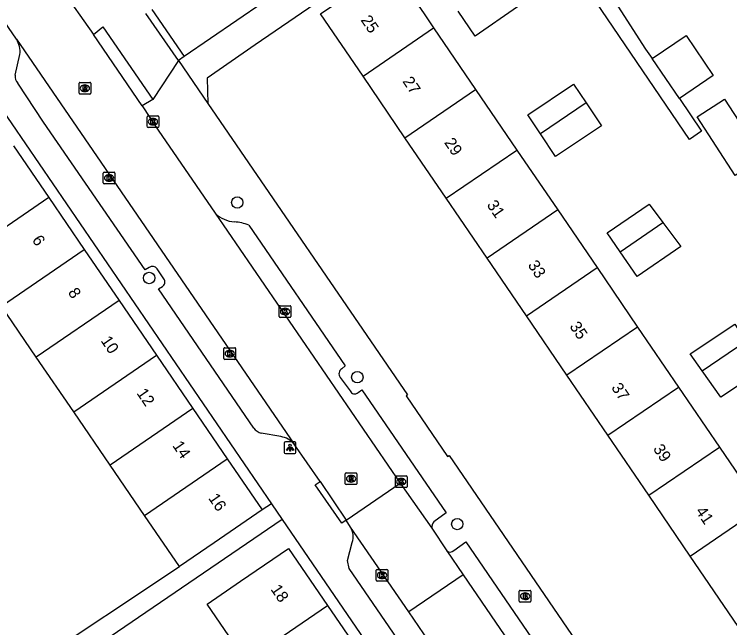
# Model space of a CAD drawing. Extents: x 157466 to 158888, y 383063 to 384677.
# Drawn here: x 158264 to 158325.5, y 383541.6 to 383594.3 of the extents above; entities that cross this region are included whole.
import ezdxf

# ---------------------------------------------------------------- set-up
doc = ezdxf.new("R2010")
doc.units = 0
for name, color, linetype in [('IMGEO_Boom', 7, 'Continuous'), ('IMGEO_Brandkraan', 7, 'Continuous'), ('IMGEO_Kolk', 7, 'Continuous'), ('IMGEO_Lichtpunt', 7, 'Continuous'), ('IMGEO_Pand', 7, 'Continuous'), ('IMGEO_Pand_nummerreeks', 7, 'Continuous'), ('IMGEO_Rijbaan_lokaal_open', 7, 'Continuous'), ('IMGEO_Rioolput', 7, 'Continuous'), ('IMGEO_Voetpad_open', 7, 'Continuous')]:
    doc.layers.add(name, color=color, linetype=linetype)

msp = doc.modelspace()

# ---------------------------------------------------------------- linework, layer by layer
at = {"layer": 'IMGEO_Boom'}
for centre in [(158283.176, 383578.158), (158275.601, 383571.669), (158293.495, 383563.147), (158302.088, 383550.528)]:
    msp.add_circle(centre, 0.489, dxfattribs=at)
at = {"layer": 'IMGEO_Brandkraan'}
for p, q in [((158307.414, 383543.907), (158307.414, 383544.759)), ((158307.489, 383544.833), (158308.341, 383544.833)), ((158307.902, 383544.613), (158307.927, 383544.613)), ((158308.415, 383544.759), (158308.415, 383543.907)), ((158308.341, 383543.833), (158307.489, 383543.833)), ((158307.925, 383544.053), (158307.9, 383544.053))]:
    msp.add_line(p, q, dxfattribs=at)
for points in [[(158307.414, 383543.907), (158307.414, 383544.759)], [(158307.489, 383544.833), (158308.341, 383544.833)], [(158307.762, 383544.533), (158307.762, 383544.133), (158307.975, 383544.133)], [(158307.993, 383544.533), (158307.762, 383544.533)], [(158307.941, 383544.452), (158307.887, 383544.452), (158307.887, 383544.376)], [(158307.887, 383544.376), (158307.94, 383544.376)], [(158307.949, 383544.3), (158307.887, 383544.3), (158307.887, 383544.219)], [(158308.415, 383544.759), (158308.415, 383543.907)], [(158308.341, 383543.833), (158307.489, 383543.833)], [(158307.887, 383544.219), (158307.949, 383544.219)]]:
    msp.add_lwpolyline(points, dxfattribs=at)
for centre, radius, start, end in [((158307.491, 383544.757), 0.0765, 91.55205, 178.44795), ((158307.491, 383544.757), 0.0765, 91.55205, 178.44795), ((158307.942, 383544.414), 0.0379, 267.82845, 90.93552), ((158307.95, 383544.259), 0.0404, 269.87594, 90.50774), ((158307.997, 383544.388), 0.145, 59.4692, 91.53667), ((158308.022, 383544.435), 0.0922, 285.51372, 58.15012), ((158308.027, 383544.243), 0.105, 301.31148, 78.98903), ((158308.339, 383544.757), 0.0765, 1.55205, 88.44795), ((158308.339, 383544.757), 0.0765, 1.55205, 88.44795), ((158307.491, 383543.909), 0.0765, 181.55205, 268.44795), ((158307.491, 383543.909), 0.0765, 181.55205, 268.44795), ((158307.981, 383544.384), 0.251, 268.66757, 293.53466), ((158308.339, 383543.909), 0.0765, 271.55205, 358.44795), ((158308.339, 383543.909), 0.0765, 271.55205, 358.44795)]:
    msp.add_arc(centre, radius, start, end, dxfattribs=at)
for centre, major_axis, ratio, start_param, end_param in [((158307.901, 383544.333), (-0.387, 0.002), 0.722429, 4.712389, 7.853982), ((158307.926, 383544.333), (-0.39, 0.002), 0.717154, 1.570796, 4.712389)]:
    msp.add_ellipse(centre, major_axis=major_axis, ratio=ratio, start_param=start_param, end_param=end_param, dxfattribs=at)
at = {"layer": 'IMGEO_Kolk'}
for p, q in [((158275.427, 383584.67), (158275.427, 383585.522)), ((158275.502, 383585.596), (158276.354, 383585.596)), ((158276.428, 383585.522), (158276.428, 383584.67)), ((158275.915, 383585.376), (158275.94, 383585.376)), ((158276.354, 383584.596), (158275.502, 383584.596)), ((158275.938, 383584.816), (158275.913, 383584.816)), ((158271.659, 383579.833), (158271.659, 383580.685)), ((158271.734, 383580.759), (158272.586, 383580.759)), ((158272.66, 383580.685), (158272.66, 383579.833)), ((158272.17, 383579.979), (158272.145, 383579.979)), ((158272.147, 383580.539), (158272.172, 383580.539)), ((158272.586, 383579.759), (158271.734, 383579.759)), ((158286.781, 383568.363), (158286.781, 383569.215)), ((158286.856, 383569.289), (158287.708, 383569.289)), ((158287.269, 383569.069), (158287.294, 383569.069)), ((158287.782, 383569.215), (158287.782, 383568.363)), ((158287.708, 383568.289), (158286.856, 383568.289)), ((158287.292, 383568.509), (158287.267, 383568.509)), ((158282.03, 383564.751), (158282.03, 383565.603)), ((158282.105, 383565.677), (158282.957, 383565.677)), ((158282.518, 383565.457), (158282.543, 383565.457)), ((158283.031, 383565.603), (158283.031, 383564.751)), ((158282.957, 383564.677), (158282.105, 383564.677)), ((158282.541, 383564.897), (158282.516, 383564.897)), ((158296.77, 383553.739), (158296.77, 383554.591)), ((158296.845, 383554.665), (158297.697, 383554.665)), ((158297.258, 383554.445), (158297.283, 383554.445)), ((158297.771, 383554.591), (158297.771, 383553.739)), ((158297.697, 383553.665), (158296.845, 383553.665)), ((158297.281, 383553.885), (158297.256, 383553.885)), ((158295.117, 383545.704), (158295.117, 383546.556)), ((158295.192, 383546.63), (158296.044, 383546.63)), ((158295.605, 383546.41), (158295.63, 383546.41)), ((158296.118, 383546.556), (158296.118, 383545.704)), ((158296.044, 383545.63), (158295.192, 383545.63)), ((158295.628, 383545.85), (158295.603, 383545.85))]:
    msp.add_line(p, q, dxfattribs=at)
for points in [[(158275.427, 383584.67), (158275.427, 383585.522)], [(158275.502, 383585.596), (158276.354, 383585.596)], [(158276.428, 383585.522), (158276.428, 383584.67)], [(158275.748, 383585.296), (158275.871, 383585.296), (158275.871, 383585.145), (158276.001, 383585.296), (158276.165, 383585.296), (158276.019, 383585.145), (158276.172, 383584.896), (158276.02, 383584.896), (158275.935, 383585.06), (158275.871, 383584.993), (158275.871, 383584.896), (158275.748, 383584.896), (158275.748, 383585.296)], [(158276.354, 383584.596), (158275.502, 383584.596)], [(158271.659, 383579.833), (158271.659, 383580.685)], [(158271.734, 383580.759), (158272.586, 383580.759)], [(158272.66, 383580.685), (158272.66, 383579.833)], [(158271.98, 383580.459), (158272.103, 383580.459), (158272.103, 383580.308), (158272.233, 383580.459), (158272.397, 383580.459), (158272.251, 383580.308), (158272.404, 383580.059), (158272.252, 383580.059), (158272.167, 383580.223), (158272.103, 383580.156), (158272.103, 383580.059), (158271.98, 383580.059), (158271.98, 383580.459)], [(158272.586, 383579.759), (158271.734, 383579.759)], [(158286.781, 383568.363), (158286.781, 383569.215)], [(158286.856, 383569.289), (158287.708, 383569.289)], [(158287.102, 383568.989), (158287.225, 383568.989), (158287.225, 383568.838), (158287.355, 383568.989), (158287.519, 383568.989), (158287.373, 383568.838), (158287.526, 383568.589), (158287.374, 383568.589), (158287.289, 383568.753), (158287.225, 383568.686), (158287.225, 383568.589), (158287.102, 383568.589), (158287.102, 383568.989)], [(158287.782, 383569.215), (158287.782, 383568.363)], [(158287.708, 383568.289), (158286.856, 383568.289)], [(158282.03, 383564.751), (158282.03, 383565.603)], [(158282.105, 383565.677), (158282.957, 383565.677)], [(158282.351, 383565.377), (158282.474, 383565.377), (158282.474, 383565.226), (158282.604, 383565.377), (158282.768, 383565.377), (158282.622, 383565.226), (158282.775, 383564.977), (158282.623, 383564.977), (158282.538, 383565.141), (158282.474, 383565.074), (158282.474, 383564.977), (158282.351, 383564.977), (158282.351, 383565.377)], [(158283.031, 383565.603), (158283.031, 383564.751)], [(158282.957, 383564.677), (158282.105, 383564.677)], [(158296.77, 383553.739), (158296.77, 383554.591)], [(158296.845, 383554.665), (158297.697, 383554.665)], [(158297.091, 383554.365), (158297.214, 383554.365), (158297.214, 383554.214), (158297.344, 383554.365), (158297.508, 383554.365), (158297.362, 383554.214), (158297.515, 383553.965), (158297.363, 383553.965), (158297.278, 383554.129), (158297.214, 383554.062), (158297.214, 383553.965), (158297.091, 383553.965), (158297.091, 383554.365)], [(158297.771, 383554.591), (158297.771, 383553.739)], [(158297.697, 383553.665), (158296.845, 383553.665)], [(158295.117, 383545.704), (158295.117, 383546.556)], [(158295.192, 383546.63), (158296.044, 383546.63)], [(158295.438, 383546.33), (158295.561, 383546.33), (158295.561, 383546.179), (158295.691, 383546.33), (158295.855, 383546.33), (158295.709, 383546.179), (158295.862, 383545.93), (158295.71, 383545.93), (158295.625, 383546.094), (158295.561, 383546.027), (158295.561, 383545.93), (158295.438, 383545.93), (158295.438, 383546.33)], [(158296.118, 383546.556), (158296.118, 383545.704)], [(158296.044, 383545.63), (158295.192, 383545.63)]]:
    msp.add_lwpolyline(points, dxfattribs=at)
for centre, start, end in [((158275.504, 383585.52), 91.55205, 178.44795), ((158275.504, 383585.52), 91.55205, 178.44795), ((158276.352, 383585.52), 1.55205, 88.44795), ((158276.352, 383585.52), 1.55205, 88.44795), ((158275.504, 383584.672), 181.55205, 268.44795), ((158275.504, 383584.672), 181.55205, 268.44795), ((158276.352, 383584.672), 271.55205, 358.44795), ((158276.352, 383584.672), 271.55205, 358.44795), ((158271.736, 383580.683), 91.55205, 178.44795), ((158271.736, 383580.683), 91.55205, 178.44795), ((158272.584, 383580.683), 1.55205, 88.44795), ((158272.584, 383580.683), 1.55205, 88.44795), ((158271.736, 383579.835), 181.55205, 268.44795), ((158271.736, 383579.835), 181.55205, 268.44795), ((158272.584, 383579.835), 271.55205, 358.44795), ((158272.584, 383579.835), 271.55205, 358.44795), ((158286.858, 383569.213), 91.55205, 178.44795), ((158286.858, 383569.213), 91.55205, 178.44795), ((158287.706, 383569.213), 1.55205, 88.44795), ((158287.706, 383569.213), 1.55205, 88.44795), ((158286.858, 383568.365), 181.55205, 268.44795), ((158286.858, 383568.365), 181.55205, 268.44795), ((158287.706, 383568.365), 271.55205, 358.44795), ((158287.706, 383568.365), 271.55205, 358.44795), ((158282.107, 383565.601), 91.55205, 178.44795), ((158282.107, 383565.601), 91.55205, 178.44795), ((158282.955, 383565.601), 1.55205, 88.44795), ((158282.955, 383565.601), 1.55205, 88.44795), ((158282.107, 383564.753), 181.55205, 268.44795), ((158282.107, 383564.753), 181.55205, 268.44795), ((158282.955, 383564.753), 271.55205, 358.44795), ((158282.955, 383564.753), 271.55205, 358.44795), ((158296.847, 383554.589), 91.55205, 178.44795), ((158296.847, 383554.589), 91.55205, 178.44795), ((158297.695, 383554.589), 1.55205, 88.44795), ((158297.695, 383554.589), 1.55205, 88.44795), ((158296.847, 383553.741), 181.55205, 268.44795), ((158296.847, 383553.741), 181.55205, 268.44795), ((158297.695, 383553.741), 271.55205, 358.44795), ((158297.695, 383553.741), 271.55205, 358.44795), ((158295.194, 383546.554), 91.55205, 178.44795), ((158295.194, 383546.554), 91.55205, 178.44795), ((158296.042, 383546.554), 1.55205, 88.44795), ((158296.042, 383546.554), 1.55205, 88.44795), ((158295.194, 383545.706), 181.55205, 268.44795), ((158295.194, 383545.706), 181.55205, 268.44795), ((158296.042, 383545.706), 271.55205, 358.44795), ((158296.042, 383545.706), 271.55205, 358.44795)]:
    msp.add_arc(centre, 0.0765, start, end, dxfattribs=at)
for centre, major_axis, ratio, start_param, end_param in [((158275.914, 383585.096), (-0.387, 0.002), 0.722429, 4.712389, 7.853982), ((158275.939, 383585.096), (-0.39, 0.002), 0.717154, 1.570796, 4.712389), ((158272.146, 383580.259), (-0.387, 0.002), 0.722429, 4.712389, 7.853982), ((158272.171, 383580.259), (-0.39, 0.002), 0.717154, 1.570796, 4.712389), ((158287.268, 383568.789), (-0.387, 0.002), 0.722429, 4.712389, 7.853982), ((158287.293, 383568.789), (-0.39, 0.002), 0.717154, 1.570796, 4.712389), ((158282.517, 383565.177), (-0.387, 0.002), 0.722429, 4.712389, 7.853982), ((158282.542, 383565.177), (-0.39, 0.002), 0.717154, 1.570796, 4.712389), ((158297.257, 383554.165), (-0.387, 0.002), 0.722429, 4.712389, 7.853982), ((158297.282, 383554.165), (-0.39, 0.002), 0.717154, 1.570796, 4.712389), ((158295.604, 383546.13), (-0.387, 0.002), 0.722429, 4.712389, 7.853982), ((158295.629, 383546.13), (-0.39, 0.002), 0.717154, 1.570796, 4.712389)]:
    msp.add_ellipse(centre, major_axis=major_axis, ratio=ratio, start_param=start_param, end_param=end_param, dxfattribs=at)
at = {"layer": 'IMGEO_Lichtpunt'}
for p, q in [((158287.218, 383557.485), (158287.218, 383556.678)), ((158287.218, 383557.485), (158287.218, 383556.678)), ((158288.12, 383557.58), (158287.312, 383557.58)), ((158288.12, 383557.58), (158287.312, 383557.58)), ((158288.214, 383556.678), (158288.214, 383557.485)), ((158288.214, 383556.678), (158288.214, 383557.485)), ((158287.312, 383556.584), (158288.12, 383556.584)), ((158287.312, 383556.584), (158288.12, 383556.584))]:
    msp.add_line(p, q, dxfattribs=at)
for points in [[(158287.592, 383557.149), (158287.631, 383557.121), (158287.443, 383556.859), (158287.405, 383556.886), (158287.592, 383557.149)], [(158287.694, 383557.101), (158287.741, 383557.101), (158287.741, 383556.779), (158287.694, 383556.779), (158287.694, 383557.101)], [(158287.804, 383557.121), (158287.842, 383557.148), (158288.029, 383556.886), (158287.99, 383556.858), (158287.804, 383557.121)]]:
    msp.add_lwpolyline(points, dxfattribs=at)
msp.add_circle((158287.717, 383557.283), 0.0994, dxfattribs=at)
for centre, start, end in [((158287.312, 383557.485), 90, 180), ((158287.312, 383557.485), 90, 180), ((158288.12, 383557.485), 0, 90), ((158288.12, 383557.485), 0, 90), ((158287.312, 383556.678), 180, 270), ((158287.312, 383556.678), 180, 270), ((158288.12, 383556.678), 270, 0), ((158288.12, 383556.678), 270, 360)]:
    msp.add_arc(centre, 0.0946, start, end, dxfattribs=at)
at = {"layer": 'IMGEO_Pand'}
for points in [[(158293.982, 383589.013), (158290.337, 383594.357), (158296.41, 383598.499), (158299.227, 383594.369), (158300.055, 383593.156)], [(158305.807, 383597.08), (158307.269, 383594.953), (158303.615, 383592.442), (158302.17, 383594.6)], [(158293.982, 383589.013), (158300.055, 383593.156)], [(158300.055, 383593.156), (158303.664, 383587.864)], [(158318.835, 383590.526), (158321.755, 383592.509), (158324.096, 383589.061), (158321.177, 383587.078)], [(158321.177, 383587.078), (158318.835, 383590.526)], [(158297.591, 383583.722), (158293.982, 383589.013)], [(158309.238, 383584.046), (158308.143, 383585.681), (158312.082, 383588.319), (158313.154, 383586.717)], [(158297.591, 383583.722), (158303.664, 383587.864)], [(158303.664, 383587.864), (158307.212, 383582.663)], [(158322.707, 383585.502), (158325.052, 383587.032), (158328.329, 383582.009), (158325.984, 383580.479), (158324.339, 383582.986), (158322.707, 383585.502)], [(158313.154, 383586.717), (158314.475, 383584.745), (158310.536, 383582.108), (158309.238, 383584.046)], [(158313.154, 383586.717), (158309.238, 383584.046)], [(158301.139, 383578.52), (158297.591, 383583.722)], [(158263.932, 383583.024), (158266.973, 383578.575)], [(158301.139, 383578.52), (158307.212, 383582.663)], [(158307.212, 383582.663), (158310.726, 383577.511)], [(158266.973, 383578.575), (158259.856, 383573.712)], [(158266.973, 383578.575), (158270.026, 383574.107)], [(158304.653, 383573.369), (158301.139, 383578.52)], [(158310.726, 383577.511), (158304.653, 383573.369)], [(158310.726, 383577.511), (158314.099, 383572.565)], [(158316.079, 383573.916), (158314.969, 383575.538), (158318.593, 383578.011), (158319.769, 383576.433)], [(158319.769, 383576.433), (158321.313, 383574.362), (158317.537, 383571.786), (158316.079, 383573.916)], [(158316.079, 383573.916), (158319.769, 383576.433)], [(158262.909, 383569.245), (158270.026, 383574.107)], [(158270.026, 383574.107), (158273.013, 383569.736)], [(158308.027, 383568.422), (158304.653, 383573.369)], [(158308.027, 383568.422), (158314.099, 383572.565)], [(158314.099, 383572.565), (158317.588, 383567.449)], [(158273.013, 383569.736), (158265.897, 383564.872)], [(158273.013, 383569.736), (158276.233, 383565.025)], [(158265.897, 383564.872), (158262.909, 383569.245)], [(158311.516, 383563.307), (158308.027, 383568.422)], [(158323.139, 383563.688), (158322.108, 383565.153), (158325.947, 383567.696), (158326.902, 383566.255)], [(158317.588, 383567.449), (158311.516, 383563.307)], [(158317.588, 383567.449), (158321.102, 383562.298)], [(158326.902, 383566.255), (158328.465, 383563.895), (158324.733, 383561.423), (158323.139, 383563.688)], [(158323.139, 383563.688), (158326.902, 383566.255)], [(158269.115, 383560.163), (158265.897, 383564.872)], [(158269.115, 383560.163), (158276.233, 383565.025)], [(158276.233, 383565.025), (158279.354, 383560.458)], [(158315.03, 383558.156), (158311.516, 383563.307)], [(158315.03, 383558.156), (158321.102, 383562.298)], [(158321.102, 383562.298), (158324.617, 383557.144)], [(158279.354, 383560.458), (158272.237, 383555.595)], [(158279.354, 383560.458), (158282.316, 383556.124)], [(158272.237, 383555.595), (158269.115, 383560.163)], [(158318.545, 383553.002), (158315.03, 383558.156)], [(158318.545, 383553.002), (158324.617, 383557.144)], [(158324.617, 383557.144), (158328.18, 383551.921)], [(158275.199, 383551.26), (158282.316, 383556.124)], [(158282.316, 383556.124), (158285.312, 383551.74)], [(158275.199, 383551.26), (158272.237, 383555.595)], [(158322.107, 383547.78), (158318.545, 383553.002)], [(158285.312, 383551.74), (158281.184, 383548.919), (158278.195, 383546.876)], [(158328.18, 383551.921), (158332.308, 383545.869), (158330.367, 383544.545), (158326.236, 383541.727), (158322.107, 383547.78)], [(158322.107, 383547.78), (158328.18, 383551.921)], [(158278.195, 383546.876), (158275.199, 383551.26)], [(158283.933, 383538.753), (158280.582, 383543.656), (158283.45, 383545.616), (158287.578, 383548.437), (158290.929, 383543.534)], [(158283.933, 383538.753), (158290.929, 383543.534)], [(158290.929, 383543.534), (158294.049, 383538.968)]]:
    msp.add_lwpolyline(points, dxfattribs=at)
at = {"layer": 'IMGEO_Rijbaan_lokaal_open'}
for points in [[(158333.171, 383627.939), (158309.83, 383612.03), (158306.706, 383609.901), (158296.72, 383603.094), (158278.623, 383590.71)], [(158264.184, 383592.177), (158263.501, 383593.197), (158262.585, 383594.528), (158261, 383596.831), (158259.046, 383599.735), (158258.908, 383599.874)], [(158267.986, 383596.629), (158270.806, 383592.574)], [(158275.823, 383594.75), (158278.623, 383590.71)], [(158278.116, 383590.363), (158275.305, 383594.395)], [(158274.995, 383586.467), (158270.806, 383592.574)], [(158264.184, 383592.177), (158288.053, 383557.407)], [(158278.623, 383590.71), (158278.116, 383590.363)], [(158274.995, 383586.467), (158276.368, 383584.356), (158281.287, 383577.232)], [(158281.287, 383577.232), (158297.166, 383554.041)], [(158290.293, 383554.184), (158288.053, 383557.407)], [(158290.293, 383554.184), (158292.53, 383550.856)], [(158292.53, 383550.856), (158297.166, 383554.041)], [(158297.166, 383554.041), (158299.891, 383550.174)], [(158292.914, 383550.25), (158292.53, 383550.856)], [(158297.921, 383542.978), (158292.914, 383550.25)], [(158299.891, 383550.174), (158301.18, 383548.218)], [(158301.18, 383548.218), (158302.597, 383546.178)], [(158302.597, 383546.178), (158297.921, 383542.978)], [(158302.597, 383546.178), (158310.512, 383534.601)], [(158317.262, 383514.634), (158297.921, 383542.978)]]:
    msp.add_lwpolyline(points, dxfattribs=at)
at = {"layer": 'IMGEO_Rioolput'}
for p, q in [((158269.575, 383587.548), (158269.575, 383588.4)), ((158269.65, 383588.474), (158270.502, 383588.474)), ((158270.063, 383588.254), (158270.088, 383588.254)), ((158270.576, 383588.4), (158270.576, 383587.548)), ((158270.502, 383587.474), (158269.65, 383587.474)), ((158270.086, 383587.694), (158270.061, 383587.694)), ((158292.456, 383553.996), (158292.456, 383554.848)), ((158292.531, 383554.922), (158293.383, 383554.922)), ((158293.457, 383554.848), (158293.457, 383553.996)), ((158292.967, 383554.142), (158292.942, 383554.142)), ((158292.944, 383554.702), (158292.969, 383554.702)), ((158293.383, 383553.922), (158292.531, 383553.922))]:
    msp.add_line(p, q, dxfattribs=at)
for points in [[(158269.575, 383587.548), (158269.575, 383588.4)], [(158269.65, 383588.474), (158270.502, 383588.474)], [(158270.164, 383588.172), (158269.912, 383588.174), (158269.912, 383587.774)], [(158270.09, 383588.093), (158270.036, 383588.093), (158270.036, 383588.012)], [(158270.036, 383588.012), (158270.088, 383588.012)], [(158270.576, 383588.4), (158270.576, 383587.548)], [(158270.502, 383587.474), (158269.65, 383587.474)], [(158269.912, 383587.774), (158270.036, 383587.774), (158270.036, 383587.936), (158270.047, 383587.936)], [(158270.094, 383587.907), (158270.165, 383587.774), (158270.305, 383587.774), (158270.24, 383587.9)], [(158292.456, 383553.996), (158292.456, 383554.848)], [(158292.531, 383554.922), (158293.383, 383554.922)], [(158293.457, 383554.848), (158293.457, 383553.996)], [(158293.045, 383554.62), (158292.793, 383554.622), (158292.793, 383554.222)], [(158292.793, 383554.222), (158292.917, 383554.222), (158292.917, 383554.384), (158292.928, 383554.384)], [(158292.971, 383554.541), (158292.917, 383554.541), (158292.917, 383554.46)], [(158292.917, 383554.46), (158292.969, 383554.46)], [(158292.975, 383554.355), (158293.046, 383554.222), (158293.186, 383554.222), (158293.121, 383554.348)], [(158293.383, 383553.922), (158292.531, 383553.922)]]:
    msp.add_lwpolyline(points, dxfattribs=at)
for centre, radius, start, end in [((158269.652, 383588.398), 0.0765, 91.55205, 178.44795), ((158269.652, 383588.398), 0.0765, 91.55205, 178.44795), ((158270.072, 383588.201), 0.19, 274.7715, 282.96867), ((158270.096, 383587.997), 0.0964, 77.00612, 93.18647), ((158270.11, 383588.054), 0.0378, 276.66336, 79.67722), ((158270.163, 383588.062), 0.109, 350.36119, 89.41601), ((158270.161, 383588.062), 0.112, 277.58423, 350.98172), ((158270.145, 383587.847), 0.108, 29.51342, 73.79051), ((158270.5, 383588.398), 0.0765, 1.55205, 88.44795), ((158270.5, 383588.398), 0.0765, 1.55205, 88.44795), ((158269.652, 383587.55), 0.0765, 181.55205, 268.44795), ((158269.652, 383587.55), 0.0765, 181.55205, 268.44795), ((158270.046, 383587.883), 0.0533, 26.02933, 88.69889), ((158270.5, 383587.55), 0.0765, 271.55205, 358.44795), ((158270.5, 383587.55), 0.0765, 271.55205, 358.44795), ((158292.533, 383554.846), 0.0765, 91.55205, 178.44795), ((158292.533, 383554.846), 0.0765, 91.55205, 178.44795), ((158293.381, 383554.846), 0.0765, 1.55205, 88.44795), ((158293.381, 383554.846), 0.0765, 1.55205, 88.44795), ((158292.927, 383554.331), 0.0533, 26.02933, 88.69889), ((158292.953, 383554.649), 0.19, 274.7715, 282.96867), ((158292.977, 383554.445), 0.0964, 77.00612, 93.18647), ((158292.991, 383554.502), 0.0378, 276.66336, 79.67722), ((158293.044, 383554.51), 0.109, 350.36119, 89.41601), ((158293.042, 383554.51), 0.112, 277.58423, 350.98172), ((158293.026, 383554.295), 0.108, 29.51342, 73.79051), ((158292.533, 383553.998), 0.0765, 181.55205, 268.44795), ((158292.533, 383553.998), 0.0765, 181.55205, 268.44795), ((158293.381, 383553.998), 0.0765, 271.55205, 358.44795), ((158293.381, 383553.998), 0.0765, 271.55205, 358.44795)]:
    msp.add_arc(centre, radius, start, end, dxfattribs=at)
for centre, major_axis, ratio, start_param, end_param in [((158270.062, 383587.974), (-0.387, 0.002), 0.722429, 4.712389, 7.853982), ((158270.087, 383587.974), (-0.39, 0.002), 0.717154, 1.570796, 4.712389), ((158292.943, 383554.422), (-0.387, 0.002), 0.722429, 4.712389, 7.853982), ((158292.968, 383554.422), (-0.39, 0.002), 0.717154, 1.570796, 4.712389)]:
    msp.add_ellipse(centre, major_axis=major_axis, ratio=ratio, start_param=start_param, end_param=end_param, dxfattribs=at)
at = {"layer": 'IMGEO_Voetpad_open'}
for points in [[(158306.438, 383606.562), (158284.721, 383591.707), (158280.579, 383588.831), (158280.654, 383586.674)], [(158321.177, 383587.078), (158323.081, 383584.275), (158322.051, 383583.576), (158306.438, 383606.562)], [(158315.377, 383595.853), (158318.263, 383591.34), (158318.835, 383590.526)], [(158270.806, 383592.574), (158271.613, 383593.241), (158275.903, 383587.003)], [(158264.091, 383589.087), (158264.497, 383590.878)], [(158278.116, 383590.363), (158275.903, 383587.003)], [(158278.116, 383590.363), (158280.654, 383586.674)], [(158260.646, 383587.833), (158261.412, 383588.358), (158286.103, 383552.281)], [(158275.604, 383572.585), (158275.264, 383572.371), (158266.512, 383585.07), (158264.301, 383588.414)], [(158275.903, 383587.003), (158274.995, 383586.467)], [(158280.654, 383586.674), (158297.815, 383561.626), (158297.69, 383561.544), (158301.237, 383556.346), (158301.401, 383556.432), (158316.985, 383533.617), (158317.112, 383533.721)], [(158284.159, 383576.219), (158292.441, 383564.128), (158292.152, 383563.862)], [(158276.869, 383571.608), (158276.302, 383572.464)], [(158284.594, 383558.767), (158276.39, 383570.751), (158276.735, 383570.927)], [(158292.007, 383563.134), (158292.872, 383561.964)], [(158293.552, 383561.819), (158293.884, 383562.049), (158301.138, 383551.491), (158300.074, 383550.728)], [(158286.925, 383558.045), (158285.233, 383558.343)], [(158292.53, 383550.856), (158292.163, 383550.61), (158289.88, 383553.911), (158290.293, 383554.184)], [(158286.103, 383552.281), (158285.312, 383551.74)], [(158286.103, 383552.281), (158287.042, 383550.909)], [(158287.042, 383550.909), (158269.172, 383538.744)], [(158287.042, 383550.909), (158313.103, 383512.83), (158312.329, 383512.22)], [(158313.727, 383516.189), (158292.804, 383546.711), (158292.643, 383547.407), (158293.059, 383548.952)], [(158301.792, 383548.262), (158302.808, 383548.999), (158310.383, 383537.936)], [(158265.465, 383538.411), (158278.195, 383546.876)]]:
    msp.add_lwpolyline(points, dxfattribs=at)
for centre, radius, start, end in [((158262.452, 383591.073), 2.054, 354.56594, 32.52893), ((158264.923, 383588.977), 0.839, 172.48686, 222.17271), ((158283.089, 383579.032), 2.547, 224.96909, 266.36943), ((158282.666, 383572.366), 4.132, 68.81093, 86.35825), ((158275.891, 383572.165), 0.508, 36.00337, 124.32738), ((158276.475, 383571.332), 0.481, 302.73695, 34.99936), ((158292.428, 383563.429), 0.514, 122.46991, 215.00105), ((158293.265, 383562.138), 0.429, 203.89269, 312.0329), ((158285.511, 383559.455), 1.147, 216.8986, 255.96993), ((158286.57, 383556.101), 1.976, 41.36244, 79.65232), ((158300.51, 383550.277), 0.627, 134.01277, 189.42787), ((158291.633, 383549.45), 1.51, 340.75587, 31.99233), ((158301.461, 383548.586), 0.463, 232.59822, 315.62624)]:
    msp.add_arc(centre, radius, start, end, dxfattribs=at)

# ---------------------------------------------------------------- texts
at = {"layer": 'IMGEO_Pand_nummerreeks'}
for s, rotation, p in [('25', 304.29796, (158293.748, 383593.828)), ('27', 304.29796, (158297.338, 383588.565)), ('29', 304.29796, (158300.927, 383583.302)), ('31', 304.29796, (158304.581, 383577.946)), ('6', 304.34875, (158265.491, 383574.931)), ('33', 304.29796, (158308.107, 383572.776)), ('8', 304.34875, (158268.576, 383570.416)), ('35', 304.29796, (158311.697, 383567.513)), ('10', 304.34875, (158271.399, 383566.284)), ('12', 304.34875, (158274.48, 383561.778)), ('37', 304.29796, (158315.287, 383562.25)), ('14', 304.34875, (158277.565, 383557.264)), ('39', 304.29796, (158318.877, 383556.987)), ('16', 304.34875, (158280.648, 383552.753)), ('41', 304.29796, (158322.531, 383551.631)), ('18', 304.34903, (158286.004, 383544.927))]:
    msp.add_text(s, height=1, rotation=rotation, dxfattribs=at).set_placement(p)

doc.saveas('drawing.dxf')
